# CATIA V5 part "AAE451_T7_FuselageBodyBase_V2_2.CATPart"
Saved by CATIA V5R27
Part number: Part7
Bounding box of the stored display mesh (mm): x -98.441 to 98.441, y -100 to 100, z -60 to 0
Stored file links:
  W:\AAE 451\AAE451_T7_FuselageAssemble_V2\AAE451_T7_FuselageBodyBase_V2_2.CATPart
  W:\AAE 451\AAE451_T7_FuselageBody.CATPart
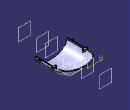
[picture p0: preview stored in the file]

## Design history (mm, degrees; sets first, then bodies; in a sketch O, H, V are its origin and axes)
Body1 (main body)
Body2
  Plane1: type Offset, RefPlane zx-plane, Offset 250, reversed
  Plane2: type Offset, RefPlane zx-plane, Offset 100
  Sketch1 on Plane1, origin (0, -250, 0), H (-1, 0, 0), V (0, 0, 1)
    circle A1 centre (0, 0) radius 24.5
    distance O A1 = 24.5
  Plane3: type Offset, RefPlane zx-plane, Offset 150, reversed
  Sketch2 on Plane2, origin (0, 100, 0), H (-1, 0, 0), V (0, 0, 1)
    construction line L1 (0, 60) -> (0, -40)
    point P1 (0, 60)
    construction line L2 (-92.2886, 30) -> (87.7114, 30)
    point P5 (0, 30)
    coincidence: P1 V, P5 L2, P5 L1
    vertical: L1 V
    horizontal: L2 H
  Sketch3 on Plane2, origin (0, 100, 0), H (-1, 0, 0), V (0, 0, 1)
    construction line L1 (0, -100) -> (0, 70)
    point P1 (0, -100)
    construction line L2 (-103.4986, 30) -> (116.5014, 30)
    point P5 (0, 30)
    point P6 (0, 60)
    construction line L3 (-60, 60) -> (60, 60)
    point P7 (-60, 60)
    reference projected curve E1 from Sketch4.E1
    ellipse A1 centre (0, 60) semi-axes 60, 35 rotation 180 from (-60, 60) to (60, 60)
    point P8 (-60, 60)
    point P9 (60, 60)
    point P10 (60, 60)
    point P11 (-60, 60)
    ellipse A2 centre (0, 60) semi-axes 60, 35 rotation 180 from (-60, 60) to (60, 60)
    "Radius" A1 = 60
    "Radius" A1 = 35
    coincidence: P1 V, P5 L2, P5 L1, P6 L1, A1 P7, P7 L3, P6 L3
    vertical: L1 V
    horizontal: L2 H, L3 H, A1 H
    tangency: L3 E1
    symmetry: P9 P10 L3, P8 P11 L3, A1 A2 L3
  Sketch4 on zx-plane, origin (0, 0, 0), H (-1, 0, 0), V (0, 0, 1)
    projected curve E1 from Sketch5.A1
  Sketch5 on Plane3, origin (0, -150, 0), H (-1, 0, 0), V (0, 0, 1)
    construction line L1 (50, 50) -> (50, -50)
    construction line L2 (50, -50) -> (-50, -50)
    construction line L3 (-50, -50) -> (-50, 50)
    construction line L4 (-50, 50) -> (50, 50)
    point P1 (50, 50)
    point P2 (50, -50)
    point P3 (-50, -50)
    point P4 (-50, 50)
    construction line L5 (0, -60) -> (0, 90)
    point P5 (0, -60)
    construction line L6 (-100, 0) -> (110, 0)
    point P7 (-100, 0)
    ellipse A1 centre (0, 0) semi-axes 90.4534, 60 rotation 0
    point P9 (0, 60)
    length L1 = 100
    length L4 = 100
    vertical: L1 V, L3 V, L5 V
    horizontal: L2 H, L4 H, L6 H, A1 H
    equidistance: L1 L3 O, L2 L4 O
    coincidence: P5 V, P7 H, P9 L5, A1 P9, P2 A1, A1 P3, P1 A1, P4 A1
    parallelism: A1 L6
  Loft1: solid, Sections (Sketch3; Sketch4; Sketch5; Sketch1)
  Sketch6 on face of Loft1, origin (0, 100, 0), H (-1, 0, 0), V (0, 0, 1)
    line L1 (-70, 95) -> (70, 95)
    line L2 (70, 95) -> (70, 60)
    line L3 (70, 60) -> (-70, 60)
    line L4 (-70, 60) -> (-70, 95)
    reference projected curve E1 from edge [face of Loft1 | face of Loft1]
    construction line L5 (-60, 60) -> (60, 60)
    length L1 = 140
    horizontal: L1 H, L3 H, L5 H
    vertical: L2 V, L4 V
    coincidence: L3 L5
    tangency: L1 E1
    symmetry: L4 L2 V
  Pocket1: profile Sketch6, direction (0, -1, 0), through (limit type 6)
  Plane4: type Offset, RefPlane Plane2, Offset 100
  Sketch7 on Plane4, origin (0, 200, 0), H (-1, 0, 0), V (0, 0, 1)
    projected line E2 (-60, 60) -> (60, 60) from edge [face of Loft1 | face of Pocket1 from Sketch6.L3]
  Pad1: profile Sketch7, direction (0, 1, 0), up to the existing solid (limit type 3)
  Sketch8 on face of Loft1, origin (0, -250, 0), H (1, 0, 0), V (0, 0, 1)
    line L1 (-97.5192, 0) -> (97.5192, 0)
    point P1 (-97.5192, 0)
    point P2 (97.5192, 0)
    projected line E1 (-62.8781, 60) -> (63.056, 60) from edge [face of Loft1 | face of Pad1]
    line L2 (-97.5192, 0) -> (-62.8781, 60)
    line L3 (97.5192, 0) -> (63.056, 60)
    angle L1 L2 = 60
    horizontal: L1 H
    symmetry: P1 P2 V
    coincidence: H L1
  Pocket2: profile Sketch8, direction (0, 1, 0), through (limit type 3)
  Shell1: ExtOffset 0, Face face of Pocket2 from Sketch8.L1, IntOffset 4
  Sketch9 on face of Pocket2 from Sketch8.L1, origin (0, 0, 0), H (1, 0, 0), V (0, 1, 0)
    arc A1 centre (93.4412, -150) radius 5 from (93.4412, -155) to (93.4412, -145) ccw
    point P1 (93.4412, -150)
    line L1 (93.4412, -145) -> (86.453, -145)
    point P2 (86.453, -145)
    line L2 (93.4412, -155) -> (86.4293, -155)
    point P3 (86.4293, -155)
    reference projected curve E1 from edge [face of Pocket2 from Sketch8.L1 | face of Shell1]
    reference projected curve E2 from edge [face of Shell1 | face of Pocket2 from Sketch8.L1]
    reference intersected line E3 through (0, -150) direction (-1, 0) from Plane3
    line L3 (86.453, -145) -> (86.4293, -155)
    distance L1 L2 = 10
    distance L3 P1 = 7
    horizontal: L1 H, L2 H
    tangency: L1 A1, L2 A1
    coincidence: P3 E1, P2 E2, E3 P1
  Pad2: profile Sketch9, direction (0, 0, -1), length 10
  RectPattern1: of Pad2, direction 1 instances 3, spacing 75, along yz-plane
  Mirror1: of RectPattern1, about yz-plane
  Plane5: type Offset, RefPlane xy-plane, Offset 55, reversed
  Sketch10 on Plane5, origin (0, 0, -55), H (1, 0, 0), V (0, 1, 0)
    line L1 (67.5, -137.75) -> (-67.5, -137.75)
    line L2 (-67.5, -137.75) -> (-67.5, -162.25)
    line L3 (-67.5, -162.25) -> (67.5, -162.25)
    line L4 (67.5, -162.25) -> (67.5, -137.75)
    construction line L5 (132.2933, -150) -> (-145.9619, -150)
    distance L4 L2 = 135
    length L2 = 24.5
    distance L5 H = 150
    horizontal: L1 H, L3 H
    vertical: L2 V, L4 V
    symmetry: L4 L2 V, L1 L3 L5
  Pad3: profile Sketch10, direction (0, 0, -1), length 12, opposite side up to the existing solid (limit type 2)
  Fillet1: radius 10, on edge [end face of Pad3 | face of Pad3 from Sketch10.L4]; edge [end face of Pad3 | face of Pad3 from Sketch10.L2]
  Sketch11 on face of RectPattern1, origin (0, 0, 0), H (1, 0, 0), V (0, 1, 0)
    circle A1 centre (93.4412, -150) radius 2.5
    reference projected arc E1 centre (93.4412, -150) radius 5 from (93.4412, -155) to (93.4412, -145) ccw from edge [face of Pad2 from Sketch9.A1 | face of RectPattern1]
    radius A1 = 2.5
    concentricity: A1 E1
  Pocket3: profile Sketch11, direction (0, 0, -1), through (limit type 3)
  RectPattern2: of Pocket3, direction 1 instances 3, spacing 75, along yz-plane
  Mirror2: of RectPattern2, about yz-plane
  Plane6 "PRINT CAPACITY": type Offset, RefPlane Plane1, Offset 150
  Sketch12 on Plane6, origin (0, -100, 0), H (-1, 0, 0), V (0, 0, 1)
    point P1 (-3.2182, -33.5)
    line L1 (124.5912, 0) -> (124.5912, -67)
    line L2 (124.5912, -67) -> (-131.0276, -67)
    line L3 (-131.0276, -67) -> (-131.0276, 0)
    line L4 (-131.0276, 0) -> (124.5912, 0)
    reference projected line E1 (-67.5, -67) -> (67.5, -67) from edge [end face of Pad3 | face of Pad3 from Sketch10.L1]
    vertical: L1 V, L3 V
    horizontal: L2 H, L4 H
    equidistance: L1 L3 P1, L2 L4 P1
    coincidence: L4 H, L2 E1
  Pocket4: profile Sketch12, direction (0, -1, 0), through (limit type 3)
  Sketch13 on face of RectPattern1, origin (0, 0, 0), H (1, 0, 0), V (0, 1, 0)
    arc A1 centre (76.4411, 0) radius 5 from (76.4411, 5) to (76.4411, -5) ccw
    point P1 (76.4411, 0)
    line L1 (76.4411, -5) -> (86.4293, -5)
    point P2 (86.4293, -5)
    line L2 (86.453, 5) -> (76.4411, 5)
    point P3 (86.453, 5)
    reference projected line E1 (86.4495, 3.5087) -> (86.4293, -5) from edge [face of RectPattern1 | face of RectPattern1]
    reference projected line E2 (86.4495, 3.5087) -> (86.4293, -5) from edge [face of RectPattern1 | face of RectPattern1]
    line L3 (86.4293, -5) -> (86.453, 5)
    construction line L4 (93.4412, 0) -> (76.4411, 0)
    point P4 (93.4412, 0)
    reference projected circle E3 centre (93.4412, 0) radius 2.5 from edge [face of RectPattern1 | face of RectPattern2]
    radius A1 = 5
    distance P1 L3 = 10
    coincidence: P3 E1, P2 E2
    horizontal: L2 H, L1 H, L4 H
    tangency: L2 A1, L1 A1
    concentricity: P4 E3
  Pad4: profile Sketch13, direction (0, 0, -1), length 10
  Sketch14 on face of Pad4, origin (77.0167, -0.3514, 0), H (1, 0, 0), V (0, 1, 0)
    point P1 (-0.5755, 0.3514)
    reference projected arc E1 centre (-0.5755, 0.3514) radius 5 from (-0.5755, 5.3514) to (-0.5755, -4.6486) ccw from edge [face of Pad4 from Sketch13.A1 | start face of Pad4]
    concentricity: P1 E1
  Hole1: placed by Sketch14, at (76.4411, 0, 0) direction (0, 0, -1), diameter 5.944, depth 8.9, V-bottom angle 120, countersink depth 7.9, countersink angle 8
  Mirror3: of Pad4, Hole1, about yz-plane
